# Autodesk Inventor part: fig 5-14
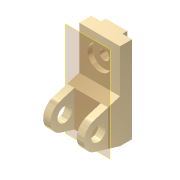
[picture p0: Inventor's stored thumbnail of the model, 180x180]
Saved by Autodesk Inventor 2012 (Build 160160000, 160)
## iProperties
Shininess: 65.0
Angle Display Precision: 2
Document Length Units: 11269
Document Angle Units: 11279
Document Time Units: 11290
Document Mass Units: 11283
Document Length Units Precision: 3
Document Angle Units Precision: 2
Compacted: False
Created: 2001-11
Part Number: fig 5-14
Document SubType Name: Modeling
Designer: Renu Muthoo
Density: 1 g/cm^3
Material: Default
Density: 0.0
Volumn: 0.0
Area: 0.0
PropertySet Name: Model Information
Control State: 0
Master: False
Checked Out: False
Author: Renu Muthoo
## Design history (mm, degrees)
node "Sketch1"
sketch "Sketch2"
  geometry: L1 (33.257, 104.664)-(33.257, -75.336); L2 (33.257, -75.336)-(8.257, -75.336); L3 (8.257, -75.336)-(-45.451, -59.045); L4 (-45.451, -1.628)-(8.257, 14.664); L5 (8.257, 14.664)-(8.257, 104.664); L6 (8.257, 104.664)-(33.257, 104.664); C1 r 15 at (-36.743, -30.336); A1 r 30 centre (-36.743, -30.336) between (-45.451, -1.628) and (-45.451, -59.045)
  constraints: 12 end point, 2 centre point, 2 equal length, 2 parallel, 2 point on circle, 2 tangent, 1 coincident, 1 perpendicular, 1 vertical
  dimensions: "d0" = 180 distance of L1.start L1.end; "d1" = 30 radius of A1; "d2" = 25 distance of L5.end L1.start; "d3" = 45 distance from line of L2 A1.centre; "d4" = 70 distance from line of L1 A1.centre; "d5" = 30 diameter of C1
extrude "Extrusion1" new body sketch "Sketch2" distance "d6" = 85; taper "d7" = 0 deg
workplane "Work Plane1"
sketch "Sketch3"
  geometry: L1 (15, 62.364)-(70, 62.364); L2 (70, 62.364)-(70, -52.386); L3 (70, -52.386)-(15, -52.386); L4 (15, -52.386)-(15, 62.364); L5 (0, -45)-(0, -28.708) reference
  constraints: 8 end point, 2 parallel, 1 horizontal, 1 perpendicular
  dimensions: "d8" = 55 distance of L1.start L1.end; "d9" = 15 distance between parallel lines of L5 L4
extrude "Extrusion2" cut sketch "Sketch3" distance "d10" = 50; taper "d11" = 0 deg
sketch "Sketch4"
  geometry: L1 (0, 25)-(85, 25) reference; L2 (0, 0)-(0, 25) reference; L3 (20, 25)-(65, 25); L4 (65, 25)-(65, 35); L5 (65, 35)-(20, 35); L6 (20, 35)-(20, 25)
  constraints: 8 end point, 2 parallel, 1 horizontal, 1 perpendicular, 1 point on line
  dimensions: "d12" = 45 distance of L4.end L5.end; "d13" = 10 distance of L3.end L4.end; "d14" = 20 distance between parallel lines of L2 L6
extrude "Extrusion3" join sketch "Sketch4" stored distance "d15" = 50; taper "d16" = 0 deg
sketch "Sketch5"
  geometry: L1 (85, 0)-(85, 90) reference; L2 (0, 90)-(85, 90) reference; 1 further point
  dimensions: "d17" = 42 distance from line of L2 point (42.5, 48); "d18" = 42.5 distance from line of L1 point (42.5, 48)
hole "Hole1" sketch "Sketch5" at (42.5, 48) diameter "d19" = 20; stored, may be unused: countersink angle "d23" = 82 deg, drill point angle "d25" = 118 deg; dims "d20" = 6, "d21" = 50, "d22" = 10, "d24" = 8
workplane "Work Plane6"
body "Solid1"
other parameters: "d26" = 0
